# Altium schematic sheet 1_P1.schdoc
size 393 x 266 mm; Symbol: Sheet-Symbol_A4; Device: Sheet-Symbol_A4; Company: 嘉立创EDA; Version: V1.0; Page Size: A4; @Project Name: NATHAN; @Page Count: 1; @Update Date: 2025-07-11; @Create Date: 2025-07-07; @Schematic Name: Schematic1_1; @Page No: 1; @Page Name: P1; @Board Name: PCB2; @Create Time: 18:07:26; @Update Time: 20:11:01; Width: 1500; Height: 1000; Region Start: 1; X Region Count: 6; Y Region Count: 4; Blade Width: 10; Title Block Position: 3
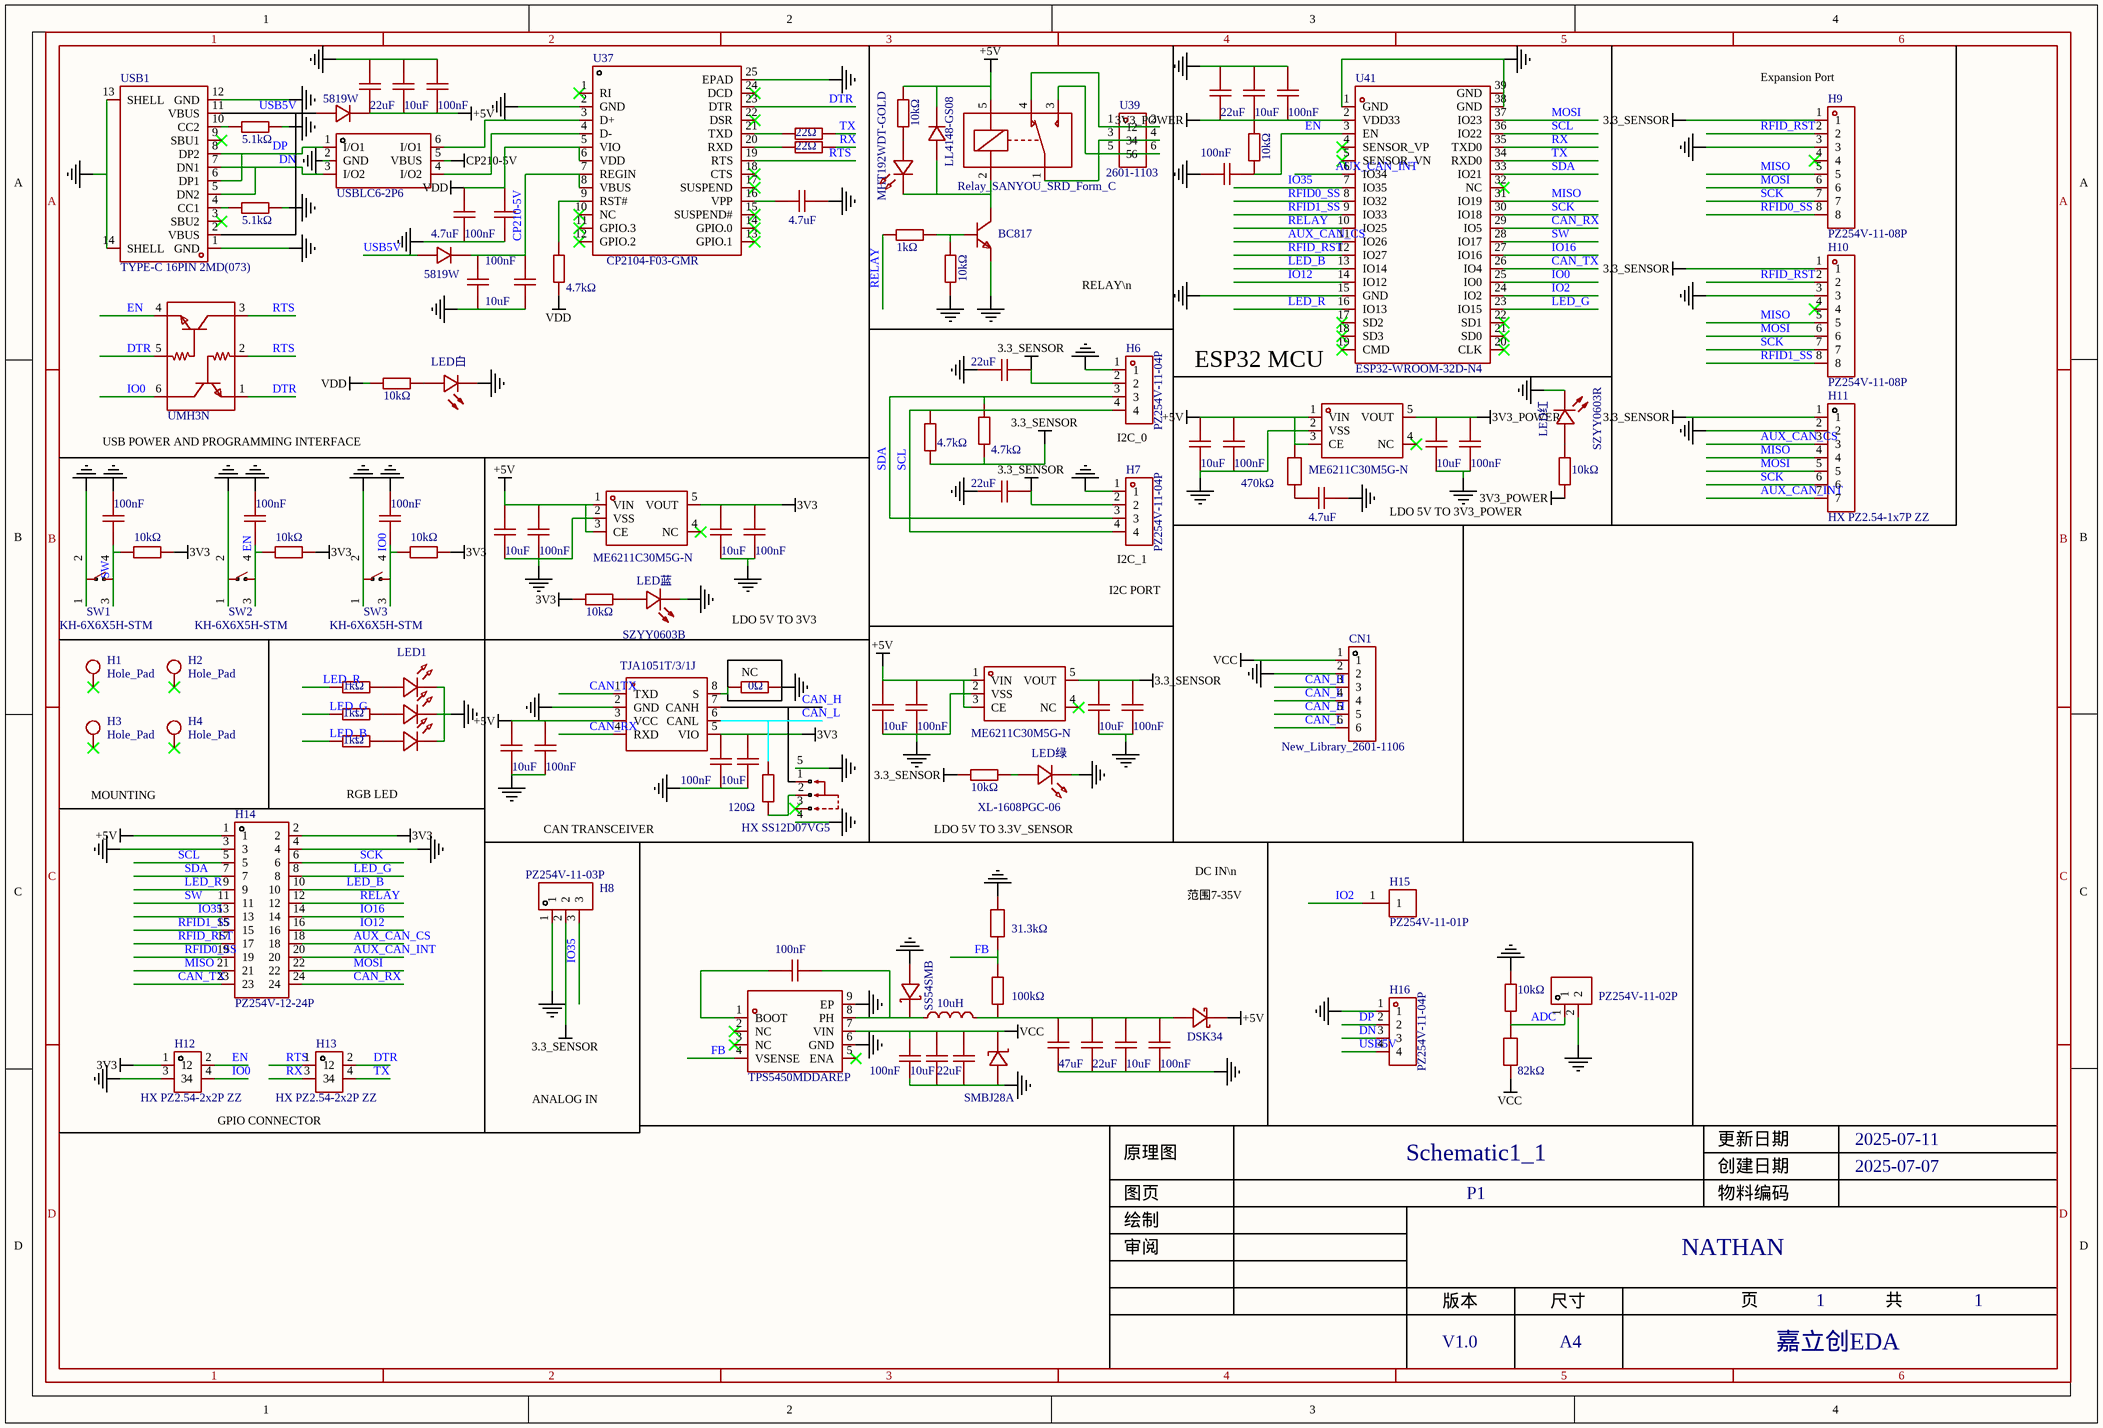
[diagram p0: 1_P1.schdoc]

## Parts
C1  22uF  [C0805]  (value not drawn)
C2  10uF  [C0603]  (value not drawn)
C3  100nF  [C0603]  (value not drawn)
C6  4.7uF  [C0603]  (value not drawn)
C9  100nF  [C0603]  (value not drawn)
C10  100nF  [C0603]  (value not drawn)
C11  100nF  [C0603]  (value not drawn)
C351  10uF  [C0603]  (value not drawn)
C352  10uF  [C0603]  (value not drawn)
C353  100nF  [C0603]  (value not drawn)
C354  100nF  [C0603]  (value not drawn)
C355  10uF  [C0603]  (value not drawn)
C356  100nF  [C0603]  (value not drawn)
C357  10uF  [C0603]  (value not drawn)
C358  100nF  [C0603]  (value not drawn)
C359  100nF  [C0603]  (value not drawn)
C360  4.7uF  [C0603]  (value not drawn)
C361  10uF  [C0603]  (value not drawn)
C362  100nF  [C0603]  (value not drawn)
C363  22uF  [C0805]  (value not drawn)
C364  22uF  [C0805]  (value not drawn)
C369  10uF  [C0603]  (value not drawn)
C370  10uF  [C0603]  (value not drawn)
C371  100nF  [C0603]  (value not drawn)
C372  100nF  [C0603]  (value not drawn)
C373  10uF  [C0603]  (value not drawn)
C374  100nF  [C0603]  (value not drawn)
C375  100nF  [C0603]  (value not drawn)
C376  10uF  [C0603]  (value not drawn)
C377  22uF  [C0805]  (value not drawn)
C378  10uF  [C0603]  (value not drawn)
C379  100nF  [C0603]  (value not drawn)
C380  100nF  [C0603]  (value not drawn)
C382  10uF  [C1206]  (value not drawn)
C383  22uF  [C1206]  (value not drawn)
C384  100nF  [C1206]  (value not drawn)
C385  47uF  [C1206]  (value not drawn)
C386  22uF  [C0805]  (value not drawn)
C387  10uF  [C0603]  (value not drawn)
C388  100nF  [C0603]  (value not drawn)
C389  100nF  [C0603]  (value not drawn)
C390  4.7uF  [C0603]  (value not drawn)
CN1  New_Library_2601-1106  [CONN-TH_2601-1106]  (value not drawn)
D1  USBLC6-2P6  [SOT-666-6_L1.6-W1.2-P0.50-LS1.6-BL]  (value not drawn)
D2  5819W  [SOD-123_L2.7-W1.6-LS3.7-FD]  (value not drawn)
D3  LL4148-GS08  [SOD-80_L3.5-W1.5-RD]  (value not drawn)
D5  SS54SMB  [SMB_L4.6-W3.6-LS5.3-RD]  (value not drawn)
D6  SMBJ28A  [SMB_L4.6-W3.6-LS5.3-L-FD]  (value not drawn)
D7  DSK34  [SOD-123FL_L2.7-W1.8-LS3.8-RD]  (value not drawn)
D8  5819W  [SOD-123_L2.7-W1.6-LS3.7-FD]  (value not drawn)
H1  value Hole_Pad  [MountingHole:MountingHole_3.2mm_M3_Pad_Via]  (hidden comment: Mechanical_MountingHole_Pad)
H2  value Hole_Pad  [MountingHole:MountingHole_3.2mm_M3_Pad_Via]  (hidden comment: Mechanical_MountingHole_Pad)
H3  value Hole_Pad  [MountingHole:MountingHole_3.2mm_M3_Pad_Via]  (hidden comment: Mechanical_MountingHole_Pad)
H4  value Hole_Pad  [MountingHole:MountingHole_3.2mm_M3_Pad_Via]  (hidden comment: Mechanical_MountingHole_Pad)
H6  PZ254V-11-04P  [HDR-TH_4P-P2.54-V-M]  (value not drawn)
H7  PZ254V-11-04P  [HDR-TH_4P-P2.54-V-M]  (value not drawn)
H8  PZ254V-11-03P  [HDR-TH_3P-P2.54-V-M]  (value not drawn)
H9  PZ254V-11-08P  [HDR-TH_8P-P2.54-V-M]  (value not drawn)
H10  PZ254V-11-08P  [HDR-TH_8P-P2.54-V-M]  (value not drawn)
H11  HX PZ2.54-1x7P ZZ  [HDR-TH_7P-P2.54-V-M]  (value not drawn)
H12  HX PZ2.54-2x2P ZZ  [HDR-TH_HX-PZ2.54-2X2P-ZZ]  (value not drawn)
H13  HX PZ2.54-2x2P ZZ  [HDR-TH_HX-PZ2.54-2X2P-ZZ]  (value not drawn)
H14  PZ254V-12-24P  [HDR-TH_24P-P2.54-V-M-R2-C12-S2.54]  (value not drawn)
H15  PZ254V-11-01P  [HDR-TH_1P-P2.54-V-M]  (value not drawn)
H16  PZ254V-11-04P  [HDR-TH_4P-P2.54-V-M]  (value not drawn)
H17  PZ254V-11-02P  [HDR-TH_2P-P2.54-V-M]  (value not drawn)
K1  Relay_SANYOU_SRD_Form_C  [Relay_THT:Relay_SPDT_SANYOU_SRD_Series_Form_C]  (value not drawn)
L12  10uH  [IND-SMD_L5.4-W5.2_FXL0530]  (value not drawn)
LED1  TC5050RGBF08-3CJH-AF53A  [LED-SMD_6P-L5.0-W5.0-TL_TC5050RGBF08]  (value not drawn)
LED白  NCD0603W1  [LED0603-RD]  (value not drawn)
LED红  SZYY0603R  [LED0603-R-RD]  (value not drawn)
LED绿  XL-1608PGC-06  [LED0603-RD_GREEN]  (value not drawn)
LED蓝  SZYY0603B  [LED0603-R-RD_BLUE]  (value not drawn)
Q1  UMH3N  [SC-70-6_L2.2-W1.3-P0.65-LS2.1-BR]  (value not drawn)
Q2  BC817  [SOT-23-3_L2.9-W1.3-P1.90-LS2.4-BR]  (value not drawn)
R1  5.1kΩ  [R0603]  (value not drawn)
R2  5.1kΩ  [R0603]  (value not drawn)
R4  22Ω  [R0603]  (value not drawn)
R5  22Ω  [R0603]  (value not drawn)
R7  10kΩ  [R0603]  (value not drawn)
R8  10kΩ  [R0603]  (value not drawn)
R9  10kΩ  [R0603]  (value not drawn)
R10  10kΩ  [R0603]  (value not drawn)
R11  10kΩ  [R0603]  (value not drawn)
R12  1kΩ  [R0603]  (value not drawn)
R13  1kΩ  [R0603]  (value not drawn)
R14  1kΩ  [R0603]  (value not drawn)
R15  0Ω  [R0603]  (value not drawn)
R17  4.7kΩ  [R0603]  (value not drawn)
R18  10kΩ  [R0603]  (value not drawn)
R19  10kΩ  [R0603]  (value not drawn)
R20  1kΩ  [R0603]  (value not drawn)
R21  4.7kΩ  [R0603]  (value not drawn)
R22  4.7kΩ  [R0603]  (value not drawn)
R23  10kΩ  [R0603]  (value not drawn)
R24  10kΩ  [R0603]  (value not drawn)
R25  10kΩ  [R0603]  (value not drawn)
R30  120Ω  [R0603]  (value not drawn)
R31  82kΩ  [R0603]  (value not drawn)
R32  10kΩ  [R0603]  (value not drawn)
R34  100kΩ  [R0603]  (value not drawn)
R35  31.3kΩ  [R0603]  (value not drawn)
R36  470kΩ  [R0603]  (value not drawn)
SW1  KH-6X6X5H-STM  [SW-SMD_4P-L6.0-W6.0-P4.50-LS9.0_H5.0]  (value not drawn)
SW2  KH-6X6X5H-STM  [SW-SMD_4P-L6.0-W6.0-P4.50-LS9.0_H5.0]  (value not drawn)
SW3  KH-6X6X5H-STM  [SW-SMD_4P-L6.0-W6.0-P4.50-LS9.0_H5.0]  (value not drawn)
U31  ME6211C30M5G-N  [SOT-23-5_L2.9-W1.6-P0.95-LS2.8-BL]  (value not drawn)
U34  TJA1051T/3/1J  [SOIC-8_L4.9-W3.9-P1.27-LS6.0-BL]  (value not drawn)
U36  HX SS12D07VG5  [SW-TH_SS12D07VG3]  (value not drawn)
U37  CP2104-F03-GMR  [QFN-24_L4.0-W4.0-P0.50-BL-EP2.7]  (value not drawn)
U38  MHT192WDT-GOLD  [LED0603-RD-YELLOW]  (value not drawn)
U39  2601-1103  [CONN-TH_6P-P3.50_2601-1103]  (value not drawn)
U40  ME6211C30M5G-N  [SOT-23-5_L2.9-W1.6-P0.95-LS2.8-BL]  (value not drawn)
U41  ESP32-WROOM-32D-N4  [WIFIM-SMD_39P-L25.5-W18.0-P1.27-BL]  (value not drawn)
U42  ME6211C30M5G-N  [SOT-23-5_L2.9-W1.6-P0.95-LS2.8-BL]  (value not drawn)
U43  TPS5450MDDAREP  [POWERPAD-SO-8_L4.9-W3.9-P1.27-LS6.0-BL-EP]  (value not drawn)
USB1  TYPE-C 16PIN 2MD(073)  [USB-C-SMD_TYPE-C-6PIN-2MD-073]  (value not drawn)

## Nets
3.3_SENSOR: C363.1 C364.1 C370.2 C372.2 H6.2 H7.2 H8.2 H9.1 H10.1 H11.1 R21.1 R22.1 R23.2 U40.5(VOUT)
3V3: C352.2 C354.2 C357.2 C358.2 H12.1 H14.2 R8.2 R9.2 R10.2 R11.2 U31.5(VOUT) U34.5(VIO)
3V3_POWER: C373.2 C375.2 C377.1 C378.1 C379.1 R24.2 R25.1 U41.2(VDD33) U42.5(VOUT)
+5V: C1.1 C2.1 C3.1 C351.2 C353.2 C355.2 C356.2 C369.2 C371.2 C374.2 C376.2 D2.2(C) D3.1(C) D7.1(K) H14.1 K1.5 R18.1 R36.2 U31.1(VIN) U31.3(CE) U34.3(VCC) U40.1(VIN) U40.3(CE) U42.1(VIN) U42.3(CE)
CP210-5V: C361.2 C362.2 D1.5(VBUS) D8.2(C) U37.7(REGIN) U37.8(VBUS)
GND: C1.2 C2.2 C3.2 C6.1 C9.2 C10.2 C11.2 C351.1 C352.1 C353.1 C354.1 C355.1 C356.1 C357.1 C358.1 C359.1 C360.1 C361.1 C362.1 C363.2 C364.2 C369.1 C370.1 C371.1 C372.1 C373.1 C374.1 C375.1 C376.1 C377.2 C378.2 C379.2 C380.2 C382.1 C383.1 C384.1 C385.1 C386.1 C387.1 C388.1 C390.1 CN1.2 D1.2(GND) D5.2(A) D6.1(A) H6.1 H7.1 H8.1 H9.3 H10.3 H11.2 H12.3 H14.3 H14.4 H16.1 H17.2 LED1.4(-) LED1.5(-) LED1.6(-) LED白.1(-) LED红.2(-) LED绿.1(K) LED蓝.2(-) Q2.2(E) R1.2 R2.2 R15.2 R19.2 R32.1 R35.2 SW1.1 SW1.2 SW2.1 SW2.2 SW3.1 SW3.2 U31.2(VSS) U34.2(GND) U36.4 U36.5 U37.2(GND) U37.25(EPAD) U40.2(VSS) U41.1(GND) U41.15(GND) U41.38(GND) U41.39(GND) U42.2(VSS) U43.6(GND) U43.9(EP) USB1.1(GND) USB1.12(GND) USB1.13(SHELL) USB1.14(SHELL)
VCC: C382.2 C383.2 C384.2 CN1.1 D6.2(K) R31.1 U43.7(VIN)
VDD: C359.2 C360.2 R7.1 R17.1 U37.5(VIO) U37.6(VDD)
ADC: H17.1 R31.2 R32.2
AUX_CAN_CS: H11.3 H14.18 U41.11(IO26)
AUX_CAN_INT: H11.7 H14.20 U41.6(IO34)
CAN_H: CN1.3 CN1.5 U34.7(CANH) U36.1
CAN_L: CN1.4 CN1.6 R30.2 U34.6(CANL)
CAN_RX: H14.24 U34.4(RXD) U41.29(IO5)
CAN_TX: H14.23 U34.1(TXD) U41.26(IO4)
DN: D1.3(I/O2) H16.3 USB1.5(DN2) USB1.7(DN1)
DP: D1.1(I/O1) H16.2 USB1.6(DP1) USB1.8(DP2)
DTR: H13.2 Q1.1(E) Q1.5(B) U37.23(DTR)
EN: C10.1 C380.1 H12.2 Q1.4(E) R9.1 R25.2 SW2.3 SW2.4 U41.3(EN)
FB: R34.2 R35.1 U43.4(VSENSE)
IO0: C11.1 H12.4 Q1.6(C) R10.1 SW3.3 SW3.4 U41.25(IO0)
IO2: H15.1 U41.24(IO2)
IO12: H14.16 U41.14(IO12)
IO16: H14.14 U41.27(IO16)
IO35: H8.3 H14.13 U41.7(IO35)
LED_B: H14.10 R14.1 U41.13(IO14)
LED_G: H14.8 R13.1 U41.23(IO15)
LED_R: H14.9 R12.1 U41.16(IO13)
MISO: H9.5 H10.5 H11.4 H14.21 U41.31(IO19)
MOSI: H9.6 H10.6 H11.5 H14.22 U41.37(IO23)
RELAY: H14.12 R20.1 U41.10(IO25)
RFID0_SS: H9.8 H14.19 U41.8(IO32)
RFID1_SS: H10.8 H14.15 U41.9(IO33)
RFID_RST: H9.2 H10.2 H14.17 U41.12(IO27)
RTS: H13.1 Q1.2(B) Q1.3(C) U37.19(RTS)
RX: H13.3 R5.2 U41.35(TXD0)
SCK: H9.7 H10.7 H11.6 H14.6 U41.30(IO18)
SCL: H6.4 H7.4 H14.5 R21.2 U41.36(IO22)
SDA: H6.3 H7.3 H14.7 R22.2 U41.33(IO21)
SW: C9.1 H14.11 R8.1 SW1.3 SW1.4 U41.28(IO17)
TX: H13.4 R4.2 U41.34(RXD0)
USB5V: D2.1(A) D8.1(A) H16.4 USB1.2(VBUS) USB1.11(VBUS)
NetC6_2: C6.2 U37.16(VPP)
NetC385_2: C385.2 C386.2 C387.2 C388.2 D7.2(A) L12.2 R34.1
NetC389_1: C389.1 D5.1(K) L12.1 U43.8(PH)
NetC389_2: C389.2 U43.1(BOOT)
NetC390_2: C390.2 R36.1
NetD1_4: D1.4(I/O2) U37.4(D-)
NetD1_6: D1.6(I/O1) U37.3(D+)
NetD3_2: D3.2(A) K1.2 Q2.3(C) U38.1(K)
NetK1_1: K1.1 U39.3 U39.4
NetK1_3: K1.3 U39.5 U39.6
NetK1_4: K1.4 U39.1 U39.2
NetLED1_1: LED1.1(+) R12.2
NetLED1_2: LED1.2(+) R13.2
NetLED1_3: LED1.3(+) R14.2
NetLED白_2: LED白.2(+) R7.2
NetLED红_1: LED红.1(+) R24.1
NetLED绿_2: LED绿.2(A) R23.1
NetLED蓝_1: LED蓝.1(+) R11.1
NetQ2_1: Q2.1(B) R19.1 R20.2
NetR1_1: R1.1 USB1.10(CC2)
NetR2_1: R2.1 USB1.4(CC1)
NetR4_1: R4.1 U37.21(TXD)
NetR5_1: R5.1 U37.20(RXD)
NetR15_1: R15.1 U34.8(S)
NetR17_2: R17.2 U37.9(RST#)
NetR18_2: R18.2 U38.2(A)
NetR30_1: R30.1 U36.2

Not connected (* = marked no-connect by the designer): H1 1*; H2 1*; H3 1*; H4 1*; H9 4*; H10 4*; U31 4(NC)*; U36 3*; U37 1(RI)* 10(NC)* 11(GPIO.3)* 12(GPIO.2)* 13(GPIO.1)* 14(GPIO.0)* 15(SUSPEND#)* 17(SUSPEND)* 18(CTS)* 22(DSR)* 24(DCD)*; U40 4(NC)*; U41 4(SENSOR_VP)* 5(SENSOR_VN)* 17(SD2)* 18(SD3)* 19(CMD)* 20(CLK)* 21(SD0)* 22(SD1)* 32(NC)*; U42 4(NC)*; U43 2(NC)* 3(NC)* 5(ENA)*; USB1 3(SBU2)* 9(SBU1)*

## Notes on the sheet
- (near H9) Expansion Port
- RELAY\n
- ESP32 MCU
- USB POWER AND PROGRAMMING INTERFACE
- (near H6) I2C_0
- LDO 5V TO 3V3_POWER
- (near H7) I2C_1
- LDO 5V TO 3V3
- (near H7) I2C PORT
- (near R15) NC
- MOUNTING
- RGB LED
- CAN TRANSCEIVER
- LDO 5V TO 3.3V_SENSOR
- 范围7-35V
- DC IN\n
- ANALOG IN
- GPIO CONNECTOR

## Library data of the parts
C1 C363 C364 C377 C386 = CGA0805X5R226M350MT: 容值:22uF;精度:±20%;额定电压:35V;材质(温度系数):X5R;; Manufacturer: HRE(芯声); Add into BOM: yes; Tolerance: ±20%; Voltage Rated: 35V; Temperature Coefficient: X5R
C2 C351 C352 C355 C357 C361 C369 C370 C373 C376 C378 C387 = CL10A106MA8NRNC: 容值:10uF;精度:±20%;额定电压:25V;材质(温度系数):X5R;; Manufacturer: SAMSUNG(三星); Add into BOM: yes; Tolerance: ±20%; Voltage Rated: 25V; Temperature Coefficient: X5R
C3 C9-C11 C353 C354 C356 C358 C359 C362 C371 C372 C374 C375 C379 C380 C388 C389 = CGA0603X7R104K500JT: 容值:100nF;精度:±10%;额定电压:50V;温度系数:X7R;; Manufacturer: HRE(芯声); Add into BOM: yes; Tolerance: ±10%; Voltage Rating: 50V; Temperature Coefficient: X7R
C6 C360 C390 = CGA0603X5R475K250JT: 容值:4.7uF;精度:±10%;额定电压:25V;温度系数:X5R;; Manufacturer: HRE(芯声); Add into BOM: yes; Tolerance: ±10%; Voltage Rating: 25V; Temperature Coefficient: X5R
C382 = HGC1206R5106K500NSPJ: 容值:10uF;精度:±10%;额定电压:50V;温度系数:X5R;; Manufacturer: Chinocera(华瓷); Add into BOM: yes; Tolerance: ±10%; Voltage Rating: 50V; Temperature Coefficient: X5R
C383 = CGA1206X5R226M350NT: 容值:22uF;精度:±20%;额定电压:35V;温度系数:X5R;; Manufacturer: HRE(芯声); Add into BOM: yes; Tolerance: ±20%; Voltage Rating: 35V; Temperature Coefficient: X5R
C384 = CL31B104KBCNNNC: 容值:100nF;精度:±10%;额定电压:50V;材质(温度系数):X7R;; Manufacturer: SAMSUNG(三星); Add into BOM: yes; Tolerance: ±10%; Voltage Rated: 50V; Temperature Coefficient: X7R
C385 = HGC1206R5476M250NSPJ: 容值:47uF;精度:±20%;额定电压:25V;温度系数:X5R;; Manufacturer: Chinocera(华瓷); Add into BOM: yes; Tolerance: ±20%; Voltage Rating: 25V; Temperature Coefficient: X5R
CN1 = 2601-1106: Add into BOM: yes
D1 = USBLC6-2P6_C2827693: 极性:单向;反向截止电压(Vrwm):5V;最大钳位电压:14V;峰值脉冲电流(Ipp):5.5A;峰值脉冲功率(Ppp):80W;击穿电压:6V;; Manufacturer: TECH PUBLIC(台舟); Add into BOM: yes; polarity: 单向; Reverse Stand-Off Voltage (Vrwm): 5V; Maximum Clamping Voltage: 14V; Peak Pulse Current (Ipp): 5.5A; Peak Pulse Power Dissipation (Ppp): 80W; Breakdown Voltage: 6V; Reverse Leakage Current (Ir): 80nA; Number of Lines: 双路; level of protection: IEC 61000-4-2; Type: ESD
D2 D8 = 5819W: 正向压降(Vf):900mV@3A;直流反向耐压(Vr):40V;整流电流:1A;; Manufacturer: MOT(仁懋); Add into BOM: yes; Voltage - DC Reverse(Vr): 40V; Current - Rectified: 1A; Reverse Leakage Current (Ir): 1mA
D3 = LL4148-GS08: 二极管配置:-;正向压降(Vf):860mV@50mA;直流反向耐压(Vr):75V;整流电流:300mA;反向恢复时间(Trr):-;; Manufacturer: VISHAY(威世); Add into BOM: yes; Voltage - DC Reverse(Vr): 75V; Current - Rectified: 300mA; Reverse Leakage Current (Ir): 5uA@75V
D5 = SS54SMB: schottky,5A 40V VF&lt;0.55V DO-214AA SMB; Manufacturer: BORN(伯恩半导体); Add into BOM: yes
D6 = SMBJ28A: 极性:Unidirectional;峰值脉冲电流（10/1000us）:13.2A;箝位电压:45.4V;击穿电压（最小值）:31.1V;反向关断电压（典型值）:28V;; Manufacturer: JJW(捷捷微); Symbol: SMBJ28A_C356769; Add into BOM: yes
D7 = DSK34_C7502709: 二极管配置:独立式;正向压降(Vf):550mV@3A;直流反向耐压(Vr):40V;平均整流电流(Io):3A;; Manufacturer: 宏迦橙; Add into BOM: yes; Diode Configuration: 独立式; Reverse Voltage (Vr): 40V; Average Rectified Current (Io): 3A; Reverse Leakage Current (Ir): 500uA; Peak forward surge current: 80A
H1-H4 = Mechanical_MountingHole_Pad: Mounting Hole with connection; Add into BOM: yes
H6 H7 H16 = PZ254V-11-04P: 插针结构:1x4P;间距:2.54mm;行距:-;圆针/方针:方针;安装类型:直插;排数:单排;总PIN位数:4P;额定电流:3A;额定电压:250V;配合针长度:6mm;塑高:2.5mm;端接针长度:3mm;触头材质:-;工作温度范围:-40℃~+105℃;颜色:黑色;; Manufacturer: XFCN(兴飞); Symbol: PZ254V-11-04P_C2691448; Add into BOM: yes; Pin Structure: 1x4P; Pitch: 2.54mm; Circluar Pins/Square Pins: 方针; Current Rating (Max): 3A; Voltage Rating (Max): 250V
H8 = PZ254V-11-03P: 插针结构:1x3P;间距:2.54mm;行距:-;圆针/方针:方针;安装方式:直插;排数:单排;总PIN位数:3P;额定电流:3A;额定电压:250V;配合针长度:6mm;塑高:2.5mm;端接针长度:3mm;工作温度:-40℃~+105℃;颜色:黑色;; Manufacturer: XFCN(兴飞); Symbol: PZ254V-11-03P_C2937625; Add into BOM: yes; Pin Structure: 1x3P; Pitch: 2.54mm; Circluar Pins/Square Pins: 方针; Current Rating: 3A; Voltage Rating (Max): 250V
H9 H10 = PZ254V-11-08P: 插针结构:1x8P;间距:2.54mm;行距:-;圆针/方针:方针;安装类型:直插;排数:单排;总PIN位数:8P;额定电流:-;额定电压:-;配合针长度:6mm;塑高:2.5mm;端接针长度:3mm;触头材质:黄铜;触头镀层:-;工作温度范围:-40℃~+105℃;颜色:黑色;; Manufacturer: XFCN(兴飞); Add into BOM: yes; Pin Structure: 1x8P; Pitch: 2.54mm; Circluar Pins/Square Pins: 方针
H11 = HX PZ2.54-1x7P ZZ: 插针结构:1x7P;间距:2.54mm;行距:-;圆针/方针:方针;安装方式:直插;排数:单排;总PIN位数:7P;额定电流:3A;额定电压:-;配合针长度:6mm;塑高:2.5mm;端接针长度:3mm;触头材质:黄铜;触头镀层:金;工作温度:-40℃~+105℃;颜色:黑色;; Manufacturer: hanxia(韩下); Add into BOM: yes; Pin Structure: 1x7P; Pitch: 2.54mm; Circluar Pins/Square Pins: 方针; Current Rating: 3A
H12 H13 = HX PZ2.54-2x2P ZZ: 插针结构:2x2P;间距:2.54mm;行距:2.54mm;圆针/方针:方针;安装方式:直插;排数:双排;总PIN位数:4P;额定电流:3A;额定电压:-;配合针长度:6mm;塑高:2.5mm;端接针长度:3mm;触头材质:黄铜;触头镀层:金;工作温度:-40℃~+105℃;颜色:黑色;; Manufacturer: hanxia(韩下); Add into BOM: yes; Pin Structure: 2x2P; Pitch: 2.54mm; Circluar Pins/Square Pins: 方针; Current Rating: 3A
H14 = PZ254V-12-24P: 插针结构:2x12P;间距:2.54mm;行距:2.54mm;圆针/方针:方针;安装方式:直插;排数:双排;总PIN位数:24P;额定电流:-;额定电压:-;配合针长度:6mm;塑高:2.5mm;端接针长度:3mm;触头材质:黄铜;触头镀层:-;工作温度:-40℃~+105℃;颜色:黑色;; Manufacturer: XFCN(兴飞); Add into BOM: yes; Pin Structure: 2x12P; Pitch: 2.54mm; Circluar Pins/Square Pins: 方针
H15 = PZ254V-11-01P: 插针结构:1x1P;间距:2.54mm;行距:-;圆针/方针:方针;安装方式:直插;排数:单排;总PIN位数:1P;额定电流:-;额定电压:-;配合针长度:6mm;塑高:2.5mm;端接针长度:3mm;触头材质:黄铜;触头镀层:-;工作温度:-40℃~+105℃;颜色:黑色;; Manufacturer: XFCN(兴飞); Add into BOM: yes; Pin Structure: 1x1P; Pitch: 2.54mm; Circluar Pins/Square Pins: 方针
H17 = PZ254V-11-02P: 插针结构:1x2P;间距:2.54mm;行距:-;圆针/方针:方针;安装方式:直插;排数:单排;总PIN位数:2P;额定电流:-;额定电压:-;配合针长度:6mm;塑高:2.5mm;端接针长度:3mm;触头材质:黄铜;触头镀层:-;工作温度:-40℃~+105℃;颜色:黑色;; Manufacturer: XFCN(兴飞); Add into BOM: yes; Pin Structure: 1x2P; Pitch: 2.54mm; Circluar Pins/Square Pins: 方针
K1 = Relay_SANYOU_SRD_Form_C: Add into BOM: yes
L12 = FXL0530-100-M: 电感值:10uH;精度:±20%;额定电流:3.2A;饱和电流(Isat):3.5A;类型:一体成型电感;; Manufacturer: cjiang(长江微电); Add into BOM: yes; Tolerance: ±20%; Rated Current: 3.2A; Saturation Current (Isat): 3.5A; DC Resistance (DCR): 125mΩ; Type: 一体成型电感
LED1 = TC5050RGBF08-3CJH-AF53A: 5050RGB，0.2W 20mA; Manufacturer: TCWIN(天成); Add into BOM: yes
LED白 = NCD0603W1: 发光颜色:白色;正向电压(VF):2.6V~3.6V;功率:72mW;正向电流:5mA;透镜颜色:雾状黄透镜;发光强度:200mcd~300mcd;发光角度:130°;工作温度:-30℃~+85℃;; Manufacturer: 国星光电; Add into BOM: yes; Emitted Color: 白色; Power Dissipation: 72mW; Forward Current: 5mA; Lens Color: 雾状黄透镜; Viewing Angle: 130°
LED红 = SZYY0603R: 发光颜色:红色;功率:40mW;正向电流:20mA;主波长:615nm~630nm;二极管配置:-;透镜颜色:无色透明透镜;色温:-;发光角度:120°;载带方式:-;工作温度:-40℃~+85℃;; Manufacturer: yongyu(永裕光电); Add into BOM: yes; Emitted Color: 红色; Power Dissipation: 40mW; Forward Current: 20mA; Peak Wavelength: 645nm; Lens Color: 无色透明透镜; Viewing Angle: 120°
LED绿 = XL-1608PGC-06: 灯头类型:-;发光颜色:翠绿色;正向电压(VF):2.6V~3V;功率:75mW;正向电流:5mA;主波长:505nm~540nm;二极管配置:-;透镜颜色:绿色透镜;色温:-;发光强度:299mcd;发光角度:130°;载带方式:正贴;工作温度:-;; Manufacturer: XINGLIGHT(成兴光); Add into BOM: yes; Emitted Color: 翠绿色; Power Dissipation: 75mW; Forward Current: 5mA; Peak Wavelength: 530nm; Lens Color: 绿色透镜; Luminous Intensity: 299mcd; Viewing Angle: 130°; Mounting Sytle: 正贴
LED蓝 = SZYY0603B: 发光颜色:蓝色;功率:100mW;正向电流:5mA;主波长:460nm~475nm;二极管配置:-;透镜颜色:无色透明透镜;色温:-;发光角度:120°;载带方式:-;工作温度:-40℃~+85℃;; Manufacturer: yongyu(永裕光电); Add into BOM: yes; Emitted Color: 蓝色; Power Dissipation: 100mW; Forward Current: 5mA; Peak Wavelength: 469nm; Lens Color: 无色透明透镜; Viewing Angle: 120°
Q1 = UMH3N: 晶体管类型:-;集射极击穿电压(Vceo):50V;集电极电流(Ic):100mA;耗散功率(Pd):150mW;直流电流增益(hFE):100@1mA,5V;; Manufacturer: CJ(江苏长电/长晶); Add into BOM: yes; Collector - Emitter Voltage VCEO: 50V; Current - Collector(Ic): 100mA; Pd - Power Dissipation: 150mW; Input Resistor: 6.11kΩ
Q2 = BC817_C916383: 晶体管类型:NPN;集电极电流(Ic):500mA;集射极击穿电压(Vceo):45V;耗散功率(Pd):300mW;直流电流增益(hFE):-;; Manufacturer: JSMSEMI(杰盛微); Add into BOM: yes; type: NPN; Current - Collector(Ic): 500mA; Collector - Emitter Voltage VCEO: 45V; Pd - Power Dissipation: 300mW; Transition frequency(fT): 100MHz; Current - Collector Cutoff: 100nA; Vce Saturation(VCE(sat)): 700mV
R1 R2 = 0603WAF5101T5E: 电阻类型:厚膜电阻;阻值:5.1kΩ;精度:±1%;功率:100mW;最大工作电压:75V;温度系数:±100ppm/℃;; Manufacturer: UNI-ROYAL(厚声); Add into BOM: yes; Tolerance: ±1%; Power(Watts): 100mW; Overload Voltage (Max): 75V
R4 R5 = 0603WAF220JT5E: 电阻类型:厚膜电阻;阻值:22Ω;精度:±1%;功率:100mW;最大工作电压:75V;温度系数:±100ppm/℃;; Manufacturer: UNI-ROYAL(厚声); Add into BOM: yes; Tolerance: ±1%; Power(Watts): 100mW; Overload Voltage (Max): 75V
R7-R11 R18 R19 R23-R25 R32 = 0603WAF1002T5E: 电阻类型:厚膜电阻;阻值:10kΩ;精度:±1%;功率:100mW;工作电压:75V;温度系数:±100ppm/℃;; Manufacturer: UNI-ROYAL(厚声); Add into BOM: yes; Tolerance: ±1%; Power(Watts): 100mW; Voltage-Supply(Max): 75V
R12-R14 R20 = 0603WAF1001T5E: 电阻类型:厚膜电阻;阻值:1kΩ;精度:±1%;功率:100mW;最大工作电压:75V;温度系数:±100ppm/℃;; Manufacturer: UNI-ROYAL(厚声); Add into BOM: yes; Tolerance: ±1%; Power(Watts): 100mW; Overload Voltage (Max): 75V
R15 = 0603WAF0000T5E: 电阻类型:厚膜电阻;阻值:0Ω;精度:±1%;功率:100mW;最大工作电压:75V;; Manufacturer: UNI-ROYAL(厚声); Add into BOM: yes; Tolerance: ±1%; Power(Watts): 100mW; Overload Voltage (Max): 75V
R17 R21 R22 = 0603WAF4701T5E: 电阻类型:厚膜电阻;阻值:4.7kΩ;精度:±1%;功率:100mW;最大工作电压:75V;温度系数:±100ppm/℃;; Manufacturer: UNI-ROYAL(厚声); Add into BOM: yes; Tolerance: ±1%; Power(Watts): 100mW; Overload Voltage (Max): 75V
R30 = 0603WAF1200T5E: 电阻类型:厚膜电阻;阻值:120Ω;精度:±1%;功率:100mW;最大工作电压:75V;温度系数:±100ppm/℃;; Manufacturer: UNI-ROYAL(厚声); Add into BOM: yes; Tolerance: ±1%; Power(Watts): 100mW; Overload Voltage (Max): 75V
R31 = FRC0603F8202TS: 电阻类型:厚膜电阻;阻值:82kΩ;精度:±1%;功率:100mW;工作电压:75V;温度系数:±100ppm/℃;; Manufacturer: FOJAN(富捷); Add into BOM: yes; Tolerance: ±1%; Power(Watts): 100mW; Voltage-Supply(Max): 75V
R34 = 0603WAF1003T5E: 电阻类型:厚膜电阻;阻值:100kΩ;精度:±1%;功率:100mW;最大工作电压:75V;温度系数:±100ppm/℃;; Manufacturer: UNI-ROYAL(厚声); Add into BOM: yes; Tolerance: ±1%; Power(Watts): 100mW; Overload Voltage (Max): 75V
R35 = 0603WAF3132T5E: 电阻类型:厚膜电阻;阻值:31.3kΩ;精度:±1%;功率:100mW;最大工作电压:75V;温度系数:±100ppm/℃;; Manufacturer: UNI-ROYAL(厚声); Add into BOM: yes; Tolerance: ±1%; Power(Watts): 100mW; Overload Voltage (Max): 75V
R36 = FRC0603F4703TS: 电阻类型:厚膜电阻;阻值:470kΩ;精度:±1%;功率:100mW;工作电压:75V;温度系数:±100ppm/℃;; Manufacturer: FOJAN(富捷); Add into BOM: yes; Tolerance: ±1%; Power(Watts): 100mW; Voltage-Supply(Max): 75V
SW1-SW3 = KH-6X6X5H-STM: 电路结构:单刀单掷;按钮形状:圆形按钮;安装方式:立贴;开关长度:6mm;开关宽度:6mm;开关高度:5mm;带支架:不带;触点电流:50mA;额定电压(DC):12V;机械寿命:8万次;; Manufacturer: kinghelm(金航标); Add into BOM: yes; Circuit: 单刀单掷; Actuator Style: 圆形按钮; Switch Length: 6mm; Switch Height: 5mm; Strike Gundam: 不带; Contact Current: 50mA; Voltage Rating (DC): 12V; Actuator/Cap Color: 黑色; Pin Style: 鸥翼型; Mechanical Life: 8万次
U31 U40 U42 = ME6211C30M5G-N: 输出类型:固定;最大输入电压:6V;输出电压:3V;最大输出电流:500mA;电源纹波抑制比(PSRR):-;输出极性:正极;; Manufacturer: MICRONE(南京微盟); Add into BOM: yes; Output Type: 固定; Maximum Input Voltage: 6V; Output Voltage: 3V; MAX Output Current: 500mA; Dropout Voltage: 210mV@(200mA); Output Polarity: 正极; Number of Outputs: 1
U34 = TJA1051T/3/1J: 类型:-;数据速率:5Mbps;; Manufacturer: NXP(恩智浦); Add into BOM: yes; Data Rate: 5Mbps; Supply Voltage: 4.5V~5.5V; Supply Current: 5mA
U36 = HX SS12D07VG5: 电路结构:单刀双掷;安装方式:直插;开关颜色:黑色;额定电流:300mA;额定电压:50V;工作寿命:1万次;; Manufacturer: hanxia(韩下); Add into BOM: yes; Circuit: 单刀双掷; Actuator Style: 矩形柱状; Switch Height: 9.7mm; Actuator Color: 黑色; Current Rating: 300mA; Voltage Rating: 50V; Life: 1万次
U37 = CP2104-F03-GMR: 应用功能:USB转UART;接口协议:-;数据速率:2Mbps;; Manufacturer: SKYWORKS/SILICON LABS(芯科); Add into BOM: yes; Supply Voltage: 1.8V；3V~3.6V; Data Rate: 2Mbps
U38 = MHT192WDT-GOLD: 发光颜色:黄色;功率:60mW;正向电流:5mA;主波长:-;二极管配置:-;透镜颜色:雾状黄透镜;色温:-;发光角度:130°;载带方式:-;工作温度:-40℃~+85℃;; Manufacturer: MEIHUA(美华); Add into BOM: yes; Emitted Color: 黄色; Power Dissipation: 60mW; Forward Current: 5mA; Lens Color: 雾状黄透镜; Viewing Angle: 130°
U39 = 2601-1103: PCB 接线端子; 操作手柄; 1.5 mm2; 焊针间距 3.5 mm; 3极; 推入式笼夹; 1,50 mm2; 灰色; Manufacturer: WAGO(万可); Add into BOM: yes
U41 = ESP32-WROOM-32D-N4: ESP32-WROOM-32D 集成 ESP32-D0WD，功能强大，用途广泛，可以用于低功耗传感器网络和要求极高的任务，例如语音编码、音频流和 MP3 解码等。; Manufacturer: ESPRESSIF(乐鑫); Add into BOM: yes
U43 = TPS5450MDDAREP: 功能类型:降压型;输出类型:可调;工作电压:5.5V~36V;输出电压:1.221V~32.04V;输出电流:5A;; Manufacturer: TI(德州仪器); Add into BOM: yes; Function: 降压型; Output Type: 可调; Output Current: 5A; Frequency - Switching: 500kHz; Synchronous Rectifier: 否; Number of Outputs: 1; Topology: 降压式; Switch tube (built-in/external): 内置
USB1 = TYPE-C 16PIN 2MD(073): 连接器类型:Type-C;协议标准:USB 3.1;公母:母;安装方式:卧贴;触点数量:16P;端口数量:1;额定电流 - 电源:3A;工作温度:-25℃~+85℃;; Manufacturer: SHOU HAN(首韩); Add into BOM: yes; Protocol Standard: USB 3.1; Gender: 母; Number of Contacts: 16P; Number of Ports: 1; Current Rating-Power: 3A; Voltage Rating: 5V; Connect-Disconnect Life: 5千次; Detection color: 黑色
